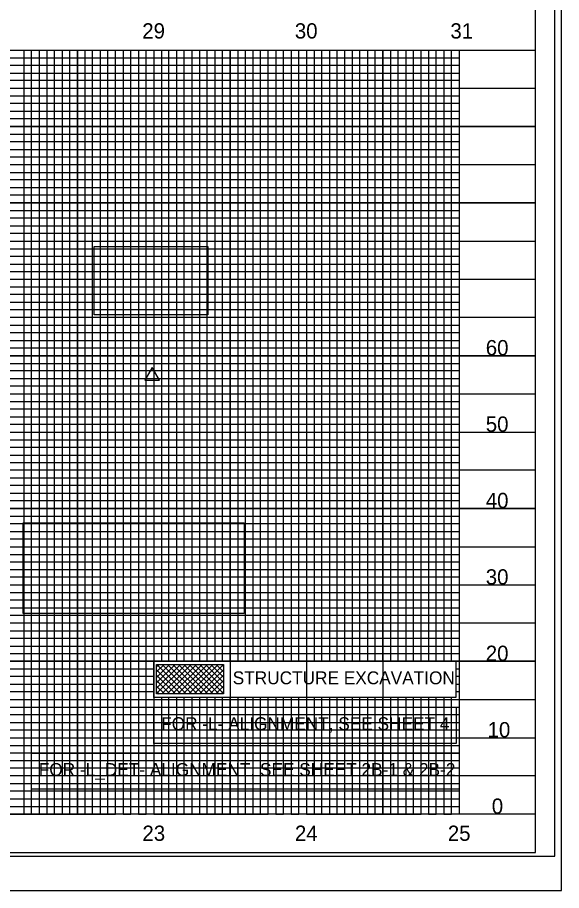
# Model space of a CAD drawing. Extents: x 1019474 to 1021161, y 504129 to 505324.
# Drawn here: x 1020802 to 1021158, y 504129 to 504701 of the extents above; entities that cross this region are included whole.
import ezdxf

# ---------------------------------------------------------------- set-up
doc = ezdxf.new("R2010")
doc.units = 0
for name, color, linetype in [('Exist Vertical Profile Horizontal Axis Label Major', 7, 'Continuous'), ('Exist Vertical Profile Vertical Axis Label', 7, 'Continuous'), ('Prop DSN Text', 7, 'Continuous'), ('Prop Grid Mask', 7, 'Continuous'), ('Prop Horizontal Alignment Station Label', 7, 'Continuous'), ('Prop Roadway Bridge', 7, 'Continuous'), ('Prop Vertical Profile Curve Label', 7, 'Continuous'), ('Sheet Cutting Line CELL', 7, 'Continuous'), ('Sheet DOT Grid CELL', 7, 'Continuous'), ('Sheet Layout Profile Border Port 2', 7, 'Continuous'), ('Sheet Plot Border Inside CELL', 7, 'Continuous'), ('Sheet Plot Border Outside CELL', 7, 'Continuous'), ('Sheet Profile CELL', 7, 'Continuous'), ('Sheet Profile Grid Major CELL', 7, 'Continuous'), ('Sheet Profile Grid Middle CELL', 7, 'Continuous'), ('Sheet Profile Grid Minor CELL', 7, 'Continuous')]:
    doc.layers.add(name, color=color, linetype=linetype)

msp = doc.modelspace()

# ---------------------------------------------------------------- linework, layer by layer
at = {"layer": 'Prop DSN Text'}
for points in [[(1020891.22, 504279.29), (1021089.01, 504279.29), (1021089.01, 504255.59), (1020891.22, 504255.59)], [(1020893.15, 504277.28), (1020936.99, 504277.28), (1020936.99, 504257.95), (1020893.15, 504257.95)]]:
    msp.add_lwpolyline(points, close=True, dxfattribs=at)
at = {"layer": 'Prop Grid Mask'}
for points in [[(1020852.19, 504550.84), (1020926.74, 504550.84), (1020926.74, 504506.07), (1020852.19, 504506.07)], [(1020805.84, 504369.95), (1020950.41, 504369.95), (1020950.41, 504310.65), (1020805.84, 504310.65)], [(1020891.34, 504249.29), (1021089.13, 504249.29), (1021089.13, 504225.59), (1020891.34, 504225.59)], [(1020811.22, 504219.29), (1021091.22, 504219.29), (1021091.22, 504195.59), (1020811.22, 504195.59)]]:
    msp.add_lwpolyline(points, close=True, dxfattribs=at)
at = {"layer": 'Prop Roadway Bridge'}
for p, q in [((1020893.15, 504258.2), (1020912.24, 504277.28)), ((1020893.15, 504261.74), (1020908.7, 504277.28)), ((1020893.15, 504265.27), (1020905.17, 504277.28)), ((1020893.15, 504268.81), (1020901.63, 504277.28)), ((1020893.15, 504272.34), (1020898.09, 504277.28)), ((1020893.15, 504275.88), (1020894.56, 504277.28)), ((1020893.22, 504277.28), (1020912.56, 504257.95)), ((1020896.44, 504257.95), (1020915.77, 504277.28)), ((1020896.76, 504277.28), (1020916.09, 504257.95)), ((1020899.97, 504257.95), (1020919.31, 504277.28)), ((1020900.29, 504277.28), (1020919.63, 504257.95)), ((1020903.51, 504257.95), (1020922.84, 504277.28)), ((1020903.83, 504277.28), (1020923.16, 504257.95)), ((1020907.04, 504257.95), (1020926.38, 504277.28)), ((1020907.36, 504277.28), (1020926.7, 504257.95)), ((1020910.58, 504257.95), (1020929.91, 504277.28)), ((1020910.9, 504277.28), (1020930.23, 504257.95)), ((1020914.11, 504257.95), (1020933.45, 504277.28)), ((1020914.43, 504277.28), (1020933.77, 504257.95)), ((1020917.65, 504257.95), (1020936.99, 504277.28)), ((1020917.97, 504277.28), (1020936.99, 504258.27)), ((1020921.5, 504277.28), (1020936.99, 504261.8)), ((1020925.04, 504277.28), (1020936.99, 504265.34)), ((1020928.58, 504277.28), (1020936.99, 504268.88)), ((1020932.11, 504277.28), (1020936.99, 504272.41)), ((1020935.65, 504277.28), (1020936.99, 504275.95)), ((1020893.15, 504273.75), (1020908.95, 504257.95)), ((1020893.15, 504270.21), (1020905.42, 504257.95)), ((1020921.18, 504257.95), (1020936.99, 504273.75)), ((1020924.72, 504257.95), (1020936.99, 504270.21)), ((1020893.15, 504266.68), (1020901.88, 504257.95)), ((1020928.26, 504257.95), (1020936.99, 504266.68)), ((1020893.15, 504263.14), (1020898.35, 504257.95)), ((1020893.15, 504259.61), (1020894.81, 504257.95)), ((1020931.79, 504257.95), (1020936.99, 504263.14)), ((1020935.33, 504257.95), (1020936.99, 504259.61))]:
    msp.add_line(p, q, dxfattribs=at)
at = {"layer": 'Prop Vertical Profile Curve Label'}
msp.add_lwpolyline([(1020885.46, 504463.24), (1020894.98, 504463.24), (1020890.22, 504471.49)], close=True, dxfattribs=at)
at = {"layer": 'Sheet Cutting Line CELL'}
msp.add_line((1019474.22, 504129.29), (1021158.22, 504129.29), dxfattribs=at)
at = {"layer": 'Sheet DOT Grid CELL'}
for p, q in [((1019641.22, 504679.29), (1021141.11, 504679.29)), ((1020841.22, 504679.29), (1020841.22, 504179.29)), ((1020891.22, 504679.29), (1020891.22, 504179.29)), ((1020941.22, 504679.29), (1020941.22, 504179.29)), ((1020991.22, 504679.29), (1020991.22, 504179.29)), ((1021041.22, 504679.29), (1021041.22, 504179.29)), ((1021091.22, 504679.29), (1021091.22, 504179.29)), ((1019641.22, 504629.29), (1021141.11, 504629.29)), ((1019641.22, 504579.29), (1021141.11, 504579.29)), ((1019641.22, 504529.29), (1021141.11, 504529.29)), ((1019641.22, 504479.29), (1021141.11, 504479.29)), ((1019641.22, 504429.29), (1021141.11, 504429.29)), ((1019641.22, 504379.29), (1021141.11, 504379.29)), ((1019641.22, 504329.29), (1021141.11, 504329.29)), ((1019641.22, 504279.29), (1021141.11, 504279.29)), ((1019641.22, 504229.29), (1021141.11, 504229.29))]:
    msp.add_line(p, q, dxfattribs=at)
at = {"layer": 'Sheet Layout Profile Border Port 2'}
msp.add_lwpolyline([(1019691.22, 504679.29), (1021091.22, 504679.29), (1021091.22, 504179.29), (1019691.22, 504179.29)], close=True, dxfattribs=at)
at = {"layer": 'Sheet Plot Border Inside CELL'}
msp.add_lwpolyline([(1019487.22, 504151.74), (1021153.72, 504151.74), (1021153.72, 505206.84), (1019487.22, 505206.84)], close=True, dxfattribs=at)
at = {"layer": 'Sheet Plot Border Outside CELL'}
msp.add_lwpolyline([(1019474.22, 504129.29), (1021158.22, 504129.29), (1021158.22, 505229.29), (1019474.22, 505229.29)], close=True, dxfattribs=at)
at = {"layer": 'Sheet Profile CELL'}
for p, q in [((1019641.22, 504679.29), (1021141.22, 504679.29)), ((1021141.22, 504179.29), (1019641.22, 504179.29)), ((1019641.22, 504154.29), (1021141.22, 504154.29))]:
    msp.add_line(p, q, dxfattribs=at)
msp.add_lwpolyline([(1021141.22, 505204.29), (1019641.22, 505204.29), (1019641.22, 504154.29), (1021141.22, 504154.29)], close=True, dxfattribs=at)
at = {"layer": 'Sheet Profile Grid Major CELL'}
for p, q in [((1020841.22, 504679.29), (1020891.22, 504679.29)), ((1020941.22, 504679.29), (1020991.22, 504679.29)), ((1021041.22, 504679.29), (1021091.22, 504679.29)), ((1021041.22, 504179.29), (1021041.22, 504179.29))]:
    msp.add_line(p, q, dxfattribs=at)
for points in [[(1020791.22, 504179.29), (1020841.22, 504179.29), (1020841.22, 504679.29), (1020891.22, 504679.29), (1020891.22, 504179.29), (1020941.22, 504179.29), (1020941.22, 504255.59)], [(1020941.22, 504279.29), (1020941.22, 504679.29), (1020991.22, 504679.29), (1020991.22, 504279.29)], [(1021041.22, 504279.29), (1021041.22, 504679.29), (1021091.22, 504679.29), (1021091.22, 504179.29)], [(1021141.22, 504629.29), (1019641.22, 504629.29)], [(1021141.22, 504579.29), (1019641.22, 504579.29), (1019641.22, 504529.29), (1021141.22, 504529.29)], [(1021141.22, 504479.29), (1019641.22, 504479.29), (1019641.22, 504429.29), (1021141.22, 504429.29)], [(1021141.22, 504379.29), (1019641.22, 504379.29), (1019641.22, 504329.29), (1021141.22, 504329.29)], [(1021141.22, 504279.29), (1019641.22, 504279.29), (1019641.22, 504279.29), (1019641.22, 504229.29), (1021141.22, 504229.29)], [(1020991.22, 504255.59), (1020991.22, 504179.29), (1021041.22, 504179.29), (1021041.22, 504179.29), (1021041.22, 504255.59)], [(1021141.22, 504179.29), (1019641.22, 504179.29)]]:
    msp.add_lwpolyline(points, dxfattribs=at)
at = {"layer": 'Sheet Profile Grid Middle CELL'}
for points in [[(1020766.22, 504679.29), (1020816.22, 504679.29), (1020816.22, 504179.29), (1020866.22, 504179.29), (1020866.22, 504679.29), (1020916.22, 504679.29), (1020916.22, 504279.29)], [(1020966.22, 504279.29), (1020966.22, 504679.29), (1021016.22, 504679.29), (1021016.22, 504279.29)], [(1021066.22, 504279.29), (1021066.22, 504679.29)], [(1019641.22, 504654.29), (1021141.22, 504654.29)], [(1021141.22, 504604.29), (1019641.22, 504604.29), (1019641.22, 504554.29), (1021141.22, 504554.29)], [(1021141.22, 504504.29), (1019641.22, 504504.29), (1019641.22, 504454.29), (1021141.22, 504454.29)], [(1021141.22, 504404.29), (1019641.22, 504404.29), (1019641.22, 504354.29), (1021141.22, 504354.29)], [(1021141.22, 504304.29), (1019641.22, 504304.29), (1019641.22, 504254.29), (1021141.22, 504254.29)], [(1020916.22, 504255.59), (1020916.22, 504179.29), (1020966.22, 504179.29), (1020966.22, 504255.59)], [(1021016.22, 504255.59), (1021016.22, 504179.29), (1021066.22, 504179.29), (1021066.22, 504255.59)], [(1021141.22, 504204.29), (1019641.22, 504204.29)]]:
    msp.add_lwpolyline(points, dxfattribs=at)
at = {"layer": 'Sheet Profile Grid Minor CELL'}
for p, q in [((1019691.22, 504674.29), (1021091.22, 504674.29)), ((1021091.22, 504669.29), (1019691.22, 504669.29)), ((1019691.22, 504664.29), (1021091.22, 504664.29)), ((1021091.22, 504659.29), (1019691.22, 504659.29)), ((1019691.22, 504649.29), (1021091.22, 504649.29)), ((1021091.22, 504644.29), (1019691.22, 504644.29)), ((1019691.22, 504639.29), (1021091.22, 504639.29)), ((1021091.22, 504634.29), (1019691.22, 504634.29)), ((1019691.22, 504624.29), (1021091.22, 504624.29)), ((1021091.22, 504619.29), (1019691.22, 504619.29)), ((1019691.22, 504614.29), (1021091.22, 504614.29)), ((1021091.22, 504609.29), (1019691.22, 504609.29)), ((1019691.22, 504599.29), (1021091.22, 504599.29)), ((1021091.22, 504594.29), (1019691.22, 504594.29)), ((1019691.22, 504589.29), (1021091.22, 504589.29)), ((1021091.22, 504584.29), (1019691.22, 504584.29)), ((1019691.22, 504574.29), (1021091.22, 504574.29)), ((1021091.22, 504569.29), (1019691.22, 504569.29)), ((1019691.22, 504564.29), (1021091.22, 504564.29)), ((1021091.22, 504559.29), (1019691.22, 504559.29)), ((1019691.22, 504549.29), (1021091.22, 504549.29)), ((1021091.22, 504544.29), (1019691.22, 504544.29)), ((1019691.22, 504539.29), (1021091.22, 504539.29)), ((1021091.22, 504534.29), (1019691.22, 504534.29)), ((1019691.22, 504524.29), (1021091.22, 504524.29)), ((1021091.22, 504519.29), (1019691.22, 504519.29)), ((1019691.22, 504514.29), (1021091.22, 504514.29)), ((1021091.22, 504509.29), (1019691.22, 504509.29)), ((1019691.22, 504499.29), (1021091.22, 504499.29)), ((1021091.22, 504494.29), (1019691.22, 504494.29)), ((1019691.22, 504489.29), (1021091.22, 504489.29)), ((1021091.22, 504484.29), (1019691.22, 504484.44)), ((1019691.22, 504474.29), (1021091.22, 504474.29)), ((1021091.22, 504469.29), (1019691.22, 504469.29)), ((1019691.22, 504464.29), (1021091.22, 504464.29)), ((1021091.22, 504459.29), (1019691.22, 504459.29)), ((1019691.22, 504449.29), (1021091.22, 504449.29)), ((1021091.22, 504444.29), (1019691.22, 504444.29)), ((1019691.22, 504439.29), (1021091.22, 504439.29)), ((1021091.22, 504434.29), (1019691.22, 504434.29)), ((1019691.22, 504424.29), (1021091.22, 504424.29)), ((1021091.22, 504419.29), (1019691.22, 504419.29)), ((1019691.22, 504414.29), (1021091.22, 504414.29)), ((1021091.22, 504409.29), (1019691.22, 504409.29)), ((1019691.22, 504399.29), (1021091.22, 504399.29)), ((1021091.22, 504394.29), (1019691.22, 504394.29)), ((1019691.22, 504389.29), (1021091.22, 504389.29)), ((1021091.22, 504384.29), (1019691.22, 504384.29)), ((1019691.22, 504374.29), (1021091.22, 504374.29)), ((1021091.22, 504369.29), (1019691.22, 504369.29)), ((1019691.22, 504364.29), (1021091.22, 504364.29)), ((1021091.22, 504359.29), (1019691.22, 504359.29)), ((1019691.22, 504349.29), (1021091.22, 504349.29)), ((1021091.22, 504344.29), (1019691.22, 504344.29)), ((1019691.22, 504339.29), (1021091.22, 504339.29)), ((1021091.22, 504334.29), (1019691.22, 504334.29)), ((1019691.22, 504324.29), (1021091.22, 504324.29)), ((1021091.22, 504319.29), (1019691.22, 504319.29)), ((1019691.22, 504314.29), (1021091.22, 504314.29)), ((1021091.22, 504309.29), (1019691.22, 504309.29)), ((1019691.22, 504299.29), (1021091.22, 504299.29)), ((1021091.22, 504294.29), (1019691.22, 504294.29)), ((1019691.22, 504289.29), (1021091.22, 504289.29)), ((1021091.22, 504284.29), (1019691.22, 504284.29)), ((1019691.22, 504274.29), (1020891.22, 504274.29)), ((1021089.01, 504274.29), (1021091.22, 504274.29)), ((1020891.22, 504269.29), (1019691.22, 504269.29)), ((1021091.22, 504269.29), (1021089.01, 504269.29)), ((1019691.22, 504264.29), (1020891.22, 504264.29)), ((1020891.22, 504259.29), (1019691.22, 504259.29)), ((1021089.01, 504264.29), (1021091.22, 504264.29)), ((1021091.22, 504259.29), (1021089.01, 504259.29)), ((1019691.22, 504249.29), (1021091.22, 504249.29)), ((1021091.22, 504244.29), (1019691.22, 504244.29)), ((1019691.22, 504239.29), (1021091.22, 504239.29)), ((1021091.22, 504234.29), (1019691.22, 504234.29)), ((1019691.22, 504224.29), (1021091.22, 504224.29)), ((1021091.22, 504219.29), (1019691.22, 504219.29)), ((1019691.22, 504214.29), (1021091.22, 504214.29)), ((1021091.22, 504209.29), (1019691.22, 504209.29)), ((1019691.22, 504199.29), (1021091.22, 504199.29)), ((1021091.22, 504194.29), (1019691.22, 504194.29)), ((1019691.22, 504189.29), (1021091.22, 504189.29)), ((1019691.22, 504184.29), (1021091.22, 504184.29)), ((1021091.22, 504184.29), (1021091.22, 504184.29))]:
    msp.add_line(p, q, dxfattribs=at)
for points in [[(1020801.22, 504679.29), (1020806.22, 504679.29), (1020806.22, 504179.29), (1020811.22, 504179.29), (1020811.22, 504679.29), (1020821.22, 504679.29), (1020821.22, 504179.29), (1020826.22, 504179.29), (1020826.22, 504679.29), (1020831.22, 504679.29), (1020831.22, 504179.29)], [(1020831.22, 504179.29), (1020836.22, 504179.29), (1020836.22, 504679.29), (1020846.22, 504679.29), (1020846.22, 504179.29), (1020851.22, 504179.29), (1020851.22, 504679.29), (1020856.22, 504679.29), (1020856.22, 504179.29), (1020861.22, 504179.29), (1020861.22, 504679.29), (1020871.22, 504679.29), (1020871.22, 504179.29), (1020876.22, 504179.29), (1020876.22, 504679.29), (1020881.22, 504679.29), (1020881.22, 504179.29), (1020886.22, 504179.29), (1020886.22, 504679.29), (1020896.22, 504679.29), (1020896.22, 504279.29)], [(1020901.22, 504279.29), (1020901.22, 504679.29), (1020906.22, 504679.29), (1020906.22, 504279.29)], [(1020911.22, 504279.29), (1020911.22, 504679.29), (1020921.22, 504679.29), (1020921.22, 504279.29)], [(1020926.22, 504279.29), (1020926.22, 504679.29), (1020931.22, 504679.29), (1020931.22, 504279.29)], [(1020936.22, 504279.29), (1020936.22, 504679.29), (1020946.22, 504679.29), (1020946.22, 504279.29)], [(1020951.22, 504279.29), (1020951.22, 504679.29), (1020956.22, 504679.29), (1020956.22, 504279.29)], [(1020961.22, 504279.29), (1020961.22, 504679.29), (1020971.22, 504679.29), (1020971.22, 504279.29)], [(1020976.22, 504279.29), (1020976.22, 504679.29), (1020981.22, 504679.29), (1020981.22, 504279.29)], [(1020986.22, 504279.29), (1020986.22, 504679.29), (1020996.22, 504679.29), (1020996.22, 504279.29)], [(1021001.22, 504279.29), (1021001.22, 504679.29), (1021006.22, 504679.29), (1021006.22, 504279.29)], [(1021011.22, 504279.29), (1021011.22, 504679.29), (1021021.22, 504679.29), (1021021.22, 504279.29)], [(1021026.22, 504279.29), (1021026.22, 504679.29), (1021031.22, 504679.29), (1021031.22, 504279.29)], [(1021036.22, 504279.29), (1021036.22, 504679.29), (1021046.22, 504679.29), (1021046.22, 504279.29)], [(1021051.22, 504279.29), (1021051.22, 504679.29), (1021056.22, 504679.29), (1021056.22, 504279.29)], [(1021061.22, 504279.29), (1021061.22, 504679.29), (1021071.22, 504679.29), (1021071.22, 504279.29)], [(1021076.22, 504279.29), (1021076.22, 504679.29), (1021081.22, 504679.29), (1021081.22, 504279.29)], [(1021086.22, 504279.29), (1021086.22, 504679.29), (1021091.22, 504679.29)], [(1020896.22, 504255.59), (1020896.22, 504179.29), (1020901.22, 504179.29), (1020901.22, 504255.59)], [(1020906.22, 504255.59), (1020906.22, 504179.29), (1020911.22, 504179.29), (1020911.22, 504255.59)], [(1020921.22, 504255.59), (1020921.22, 504179.29), (1020926.22, 504179.29), (1020926.22, 504255.59)], [(1020931.22, 504255.59), (1020931.22, 504179.29), (1020936.22, 504179.29), (1020936.22, 504255.59)], [(1020946.22, 504255.59), (1020946.22, 504179.29), (1020951.22, 504179.29), (1020951.22, 504255.59)], [(1020956.22, 504255.59), (1020956.22, 504179.29), (1020961.22, 504179.29), (1020961.22, 504255.59)], [(1020971.22, 504255.59), (1020971.22, 504179.29), (1020976.22, 504179.29), (1020976.22, 504255.59)], [(1020981.22, 504255.59), (1020981.22, 504179.29), (1020986.22, 504179.29), (1020986.22, 504255.59)], [(1020996.22, 504255.59), (1020996.22, 504179.29), (1021001.22, 504179.29), (1021001.22, 504255.59)], [(1021006.22, 504255.59), (1021006.22, 504179.29), (1021011.22, 504179.29), (1021011.22, 504255.59)], [(1021021.22, 504255.59), (1021021.22, 504179.29), (1021026.22, 504179.29), (1021026.22, 504255.59)], [(1021031.22, 504255.59), (1021031.22, 504179.29), (1021036.22, 504179.29), (1021036.22, 504255.59)], [(1021046.22, 504255.59), (1021046.22, 504179.29), (1021051.22, 504179.29), (1021051.22, 504255.59)], [(1021056.22, 504255.59), (1021056.22, 504179.29), (1021061.22, 504179.29), (1021061.22, 504255.59)], [(1021071.22, 504255.59), (1021071.22, 504179.29), (1021076.22, 504179.29), (1021076.22, 504255.59)], [(1021081.22, 504255.59), (1021081.22, 504179.29), (1021086.22, 504179.29), (1021086.22, 504255.59)]]:
    msp.add_lwpolyline(points, dxfattribs=at)

# ---------------------------------------------------------------- texts
at = {"layer": 'Exist Vertical Profile Horizontal Axis Label Major'}
for s, p in [('29', (1020883.73, 504686.86)), ('30', (1020983.61, 504686.86)), ('31', (1021085.45, 504686.86)), ('23', (1020883.83, 504161.79)), ('24', (1020983.67, 504161.79)), ('25', (1021083.77, 504161.79))]:
    msp.add_text(s, height=10, dxfattribs=at).set_placement(p)
at = {"layer": 'Exist Vertical Profile Vertical Axis Label'}
for s, p in [('60', (1021108.61, 504479.54)), ('50', (1021108.61, 504429.54)), ('40', (1021108.61, 504379.54)), ('30', (1021108.61, 504329.54)), ('20', (1021108.61, 504279.54)), ('10', (1021109.8, 504229.54)), ('0', (1021112.56, 504179.54))]:
    msp.add_text(s, height=10, dxfattribs=at).set_placement(p)
at = {"layer": 'Prop Horizontal Alignment Station Label'}
for s, p in [('STRUCTURE EXCAVATION', (1020942.94, 504264.28)), ('FOR -L- ALIGNMENT, SEE SHEET 4', (1020896.1, 504234.27)), ('FOR -L_DET- ALIGNMENT, SEE SHEET 2B-1 & 2B-2', (1020815.98, 504204.27))]:
    msp.add_text(s, height=8.4375, dxfattribs=at).set_placement(p)

doc.saveas('drawing.dxf')
